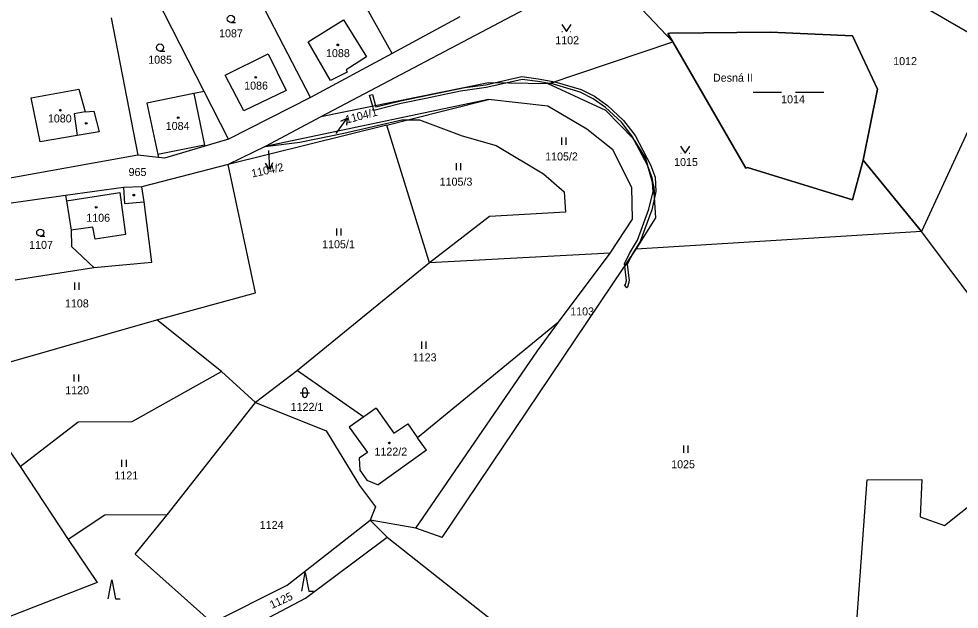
# Model space of a CAD drawing. Extents: x -670359 to -660124, y -978807 to -970072.
# Drawn here: x -669982.9 to -669783.1, y -977781.2 to -977655.6 of the extents above; entities that cross this region are included whole.
import ezdxf

# ---------------------------------------------------------------- set-up
doc = ezdxf.new("R2010")
doc.units = 0
for name, color, linetype in [('Hranice parcel', 7, 'Continuous'), ('Parcelní čísla', 7, 'Continuous'), ('Pop  PČ popisy', 7, 'Continuous'), ('Vnitřní kresba', 7, 'Continuous'), ('Věcná břemena k části', 7, 'Continuous'), ('Značky budov', 7, 'Continuous'), ('Značky kultur', 7, 'Continuous')]:
    doc.layers.add(name, color=color, linetype=linetype)

msp = doc.modelspace()

# ---------------------------------------------------------------- linework, layer by layer
at = {"layer": 'Hranice parcel'}
for p, q in [((-669900.23, -977677.12), (-669883.11, -977672.77)), ((-669913.87, -977679.97), (-669901.49, -977677.14)), ((-669904.67, -977678.25), (-669900.23, -977677.12)), ((-669901.49, -977677.14), (-669900.23, -977677.12)), ((-669900.23, -977677.12), (-669897.75, -977677.09)), ((-669897.75, -977677.09), (-669888.73, -977680.55)), ((-669923.22, -977681.85), (-669913.87, -977679.97)), ((-669888.73, -977680.55), (-669881.48, -977682.58)), ((-669930.56, -977682.8), (-669923.22, -977681.85)), ((-669881.48, -977682.58), (-669871.4, -977688.59)), ((-669871.4, -977688.59), (-669867.03, -977692.44)), ((-669867.03, -977692.44), (-669866.71, -977696.78)), ((-669882.89, -977697.69), (-669895.63, -977707.53)), ((-669866.71, -977696.78), (-669882.89, -977697.69))]:
    msp.add_line(p, q, dxfattribs=at)
for points in [[(-669903.55, -977663.02), (-669919.14, -977635.11)], [(-669773.6, -977662.93), (-669808.82, -977642.52)], [(-669920.94, -977672.36), (-669936.3, -977642.69)], [(-669858.47, -977645.13), (-669843.94, -977660.55)], [(-669943.49, -977671.09), (-669953.69, -977651.05)], [(-669871.55, -977651.52), (-669918.75, -977676.5)], [(-669963.25, -977655.43), (-669957.62, -977684.64)], [(-669921.4, -977660.53), (-669913.91, -977655.85)], [(-669913.91, -977655.85), (-669908.99, -977663.73)], [(-669889.2, -977655.23), (-669903.55, -977663.02)], [(-669823.21, -977658.51), (-669844.56, -977658.72)], [(-669805.77, -977659.28), (-669823.21, -977658.51)], [(-669916.64, -977668.73), (-669921.4, -977660.53)], [(-669870.41, -977669.5), (-669843.94, -977660.55)], [(-669844.56, -977658.72), (-669844.96, -977658.8)], [(-669844.96, -977658.8), (-669843.94, -977660.55)], [(-669828.41, -977687.39), (-669843.94, -977660.55)], [(-669800.43, -977670.6), (-669805.77, -977659.28)], [(-669939.03, -977667.59), (-669929.94, -977663.06)], [(-669929.94, -977663.06), (-669926.06, -977670.87)], [(-669903.55, -977663.02), (-669920.94, -977672.36)], [(-669908.99, -977663.73), (-669913.37, -977666.48)], [(-669773.6, -977662.93), (-669791.07, -977700.83)], [(-669913.37, -977666.48), (-669913.13, -977666.96)], [(-669935.07, -977675.24), (-669939.03, -977667.59)], [(-669913.13, -977666.96), (-669916.64, -977668.73)], [(-669980.27, -977672.47), (-669970.13, -977670.57)], [(-669970.13, -977670.57), (-669968.82, -977675.44)], [(-669883.13, -977669.25), (-669918.75, -977676.5)], [(-669870.41, -977669.5), (-669883.13, -977669.25)], [(-669858.14, -977675.1), (-669870.41, -977669.5)], [(-669978.38, -977681.81), (-669980.27, -977672.47)], [(-669945.73, -977671.55), (-669955.72, -977673.6)], [(-669943.49, -977671.09), (-669945.73, -977671.55)], [(-669938.32, -977681.25), (-669943.49, -977671.09)], [(-669920.94, -977672.36), (-669938.32, -977681.25)], [(-669926.06, -977670.87), (-669935.07, -977675.24)], [(-669803.47, -977685.72), (-669800.43, -977670.6)], [(-669955.72, -977673.6), (-669953.34, -977684.46)], [(-669883.11, -977672.77), (-669930.56, -977682.8)], [(-669870.46, -977674.21), (-669883.11, -977672.77)], [(-669862.2, -977679.12), (-669870.46, -977674.21)], [(-669968.82, -977675.44), (-669966.98, -977675.27)], [(-669966.98, -977675.27), (-669965.84, -977679.66)], [(-669918.75, -977676.5), (-669930.56, -977682.8)], [(-669852.35, -977681.06), (-669858.14, -977675.1)], [(-669904.67, -977678.25), (-669938.45, -977686.61)], [(-669895.63, -977707.53), (-669904.67, -977678.25)], [(-669970.47, -977680.48), (-669978.38, -977681.81)], [(-669965.84, -977679.66), (-669970.47, -977680.48)], [(-669856.66, -977683.48), (-669862.2, -977679.12)], [(-669938.32, -977681.25), (-669951.97, -977685.25)], [(-669849.77, -977685.28), (-669852.35, -977681.06)], [(-669953.34, -977684.46), (-669953.19, -977685.12)], [(-669930.56, -977682.8), (-669938.45, -977686.61)], [(-669852.62, -977691.53), (-669856.66, -977683.48)], [(-669957.62, -977684.64), (-669986.76, -977689.88)], [(-669953.19, -977685.12), (-669957.62, -977684.64)], [(-669951.97, -977685.25), (-669953.19, -977685.12)], [(-669847.98, -977691.34), (-669849.77, -977685.28)], [(-669803.47, -977685.72), (-669805.74, -977694.12)], [(-669791.07, -977700.83), (-669803.47, -977685.72)], [(-669938.45, -977686.61), (-669956.78, -977691.35)], [(-669932.63, -977713.9), (-669938.45, -977686.61)], [(-669828.09, -977687.23), (-669828.41, -977687.39)], [(-669805.74, -977694.12), (-669828.09, -977687.23)], [(-669960.66, -977691.53), (-669972.97, -977693.24)], [(-669956.78, -977691.35), (-669960.66, -977691.53)], [(-669956.24, -977694.54), (-669956.78, -977691.35)], [(-669852.5, -977698.24), (-669852.62, -977691.53)], [(-669847.54, -977697.97), (-669847.98, -977691.34)], [(-669972.97, -977693.24), (-669985.99, -977695.04)], [(-669972.97, -977693.24), (-669972.8, -977694.32)], [(-669972.8, -977694.32), (-669971.8, -977700.55)], [(-669954.65, -977707.4), (-669956.24, -977694.54)], [(-669857.26, -977705.46), (-669852.5, -977698.24)], [(-669851.75, -977704.63), (-669847.54, -977697.97)], [(-669971.8, -977700.55), (-669971.71, -977704.06)], [(-669791.07, -977700.83), (-669851.75, -977704.63)], [(-669764.89, -977735.76), (-669791.07, -977700.83)], [(-669971.71, -977704.06), (-669966.96, -977708.51)], [(-669857.26, -977705.46), (-669895.63, -977707.53)], [(-669892.92, -977765.93), (-669851.75, -977704.63)], [(-669868.22, -977720.15), (-669857.26, -977705.46)], [(-669983.66, -977711.17), (-669966.96, -977708.51)], [(-669966.96, -977708.51), (-669954.65, -977707.4)], [(-669895.63, -977707.53), (-669923.66, -977730.39)], [(-669953.55, -977719.62), (-669932.63, -977713.9)], [(-669996.13, -977731.83), (-669953.55, -977719.62)], [(-669939.81, -977730.65), (-669953.55, -977719.62)], [(-669868.22, -977720.15), (-669898.16, -977744.72)], [(-669872.66, -977726.25), (-669868.22, -977720.15)], [(-669898.53, -977763.96), (-669872.66, -977726.25)], [(-669923.66, -977730.39), (-669932.58, -977737.23)], [(-669923.66, -977730.39), (-669909.56, -977740.23)], [(-669958.79, -977741.23), (-669939.81, -977730.65)], [(-669932.58, -977737.23), (-669939.81, -977730.65)], [(-669993.93, -977734.4), (-669982.65, -977750.8)], [(-669951.41, -977761.08), (-669932.58, -977737.23)], [(-669932.58, -977737.23), (-669917.59, -977743.22)], [(-669907, -977738.39), (-669909.56, -977740.23)], [(-669907, -977738.39), (-669903.19, -977743.73)], [(-669909.56, -977740.23), (-669912.68, -977742.47)], [(-669982.65, -977750.8), (-669970.31, -977741.3)], [(-669970.31, -977741.3), (-669958.79, -977741.23)], [(-669912.68, -977742.47), (-669908.84, -977747.84)], [(-669903.19, -977743.73), (-669900.27, -977741.75)], [(-669900.27, -977741.75), (-669898.16, -977744.72)], [(-669917.59, -977743.22), (-669910.49, -977754.84)], [(-669896.28, -977747.38), (-669898.16, -977744.72)], [(-669908.84, -977747.84), (-669910.58, -977749.07)], [(-669896.28, -977747.38), (-669906.58, -977754.71)], [(-669910.58, -977749.07), (-669910.44, -977751.63)], [(-669982.65, -977750.8), (-669972.41, -977766.32)], [(-669910.44, -977751.63), (-669908.93, -977753.75)], [(-669908.93, -977753.75), (-669906.58, -977754.71)], [(-669805.3, -977790.58), (-669802.62, -977753.64)], [(-669802.62, -977753.64), (-669791.02, -977753.57)], [(-669791.02, -977753.57), (-669791.38, -977761.49)], [(-669910.49, -977754.84), (-669907.11, -977759.38)], [(-669786.17, -977763.37), (-669775.42, -977754.76)], [(-669907.11, -977759.38), (-669908.21, -977762.26)], [(-669964.6, -977761.16), (-669972.41, -977766.32)], [(-669951.41, -977761.08), (-669964.6, -977761.16)], [(-669958.16, -977769.43), (-669951.41, -977761.08)], [(-669925.89, -977776.03), (-669908.21, -977762.26)], [(-669908.21, -977762.26), (-669904.6, -977765.84)], [(-669898.53, -977763.96), (-669908.21, -977762.26)], [(-669791.38, -977761.49), (-669786.17, -977763.37)], [(-669892.92, -977765.93), (-669898.53, -977763.96)], [(-669972.41, -977766.32), (-669966.28, -977775.47)], [(-669921.96, -977778.81), (-669904.6, -977765.84)], [(-669904.6, -977765.84), (-669881.63, -977784.08)], [(-669941.84, -977784.04), (-669958.16, -977769.43)], [(-669966.28, -977775.47), (-669994.9, -977786.6)], [(-669941.84, -977784.04), (-669925.89, -977776.03)], [(-669942.37, -977789.56), (-669921.96, -977778.81)]]:
    msp.add_lwpolyline(points, dxfattribs=at)
at = {"layer": 'Parcelní čísla'}
for p, q in [((-669914.49, -977677.37), (-669913.11, -977676.77)), ((-669928.97, -977686.27), (-669929.65, -977687.6))]:
    msp.add_line(p, q, dxfattribs=at)
for points in [[(-669915.49, -977679.99), (-669913.11, -977676.77), (-669913.28, -977678.26)], [(-669929.86, -977683.61), (-669929.65, -977687.6), (-669930.47, -977686.35)]]:
    msp.add_lwpolyline(points, dxfattribs=at)
at = {"layer": 'Vnitřní kresba'}
for points in [[(-669945.73, -977671.55), (-669943.43, -977682.48)], [(-669968.82, -977675.44), (-669971.14, -977675.85)], [(-669971.14, -977675.85), (-669970.47, -977680.48)], [(-669943.43, -977682.48), (-669953.34, -977684.46)], [(-669960.66, -977691.53), (-669960.48, -977694.89)], [(-669972.8, -977694.32), (-669961.45, -977692.58)], [(-669961.45, -977692.58), (-669960.2, -977701.52)], [(-669960.48, -977694.89), (-669956.24, -977694.54)], [(-669967.17, -977699.96), (-669971.8, -977700.55)], [(-669966.68, -977702.52), (-669967.17, -977699.96)], [(-669960.2, -977701.52), (-669966.68, -977702.52)]]:
    msp.add_lwpolyline(points, dxfattribs=at)
at = {"layer": 'Věcná břemena k části'}
for p, q in [((-669881.89, -977669.27), (-669876.02, -977667.94)), ((-669875.98, -977668.54), (-669879.4, -977669.32)), ((-669876.02, -977667.94), (-669872.54, -977668.38)), ((-669872.63, -977668.98), (-669875.98, -977668.54)), ((-669872.54, -977668.38), (-669868.99, -977669.02)), ((-669901.82, -977673.05), (-669888.16, -977670.27)), ((-669883.58, -977670.28), (-669889.05, -977671)), ((-669888.16, -977670.27), (-669883.68, -977669.68)), ((-669883.68, -977669.68), (-669881.89, -977669.27)), ((-669879.4, -977669.32), (-669883.58, -977670.28)), ((-669870.14, -977669.41), (-669872.63, -977668.98)), ((-669908.36, -977671.86), (-669907.78, -977671.7)), ((-669907.71, -977674.25), (-669908.36, -977671.86)), ((-669907.78, -977671.7), (-669907.13, -977674.13)), ((-669896.45, -977672.57), (-669901.67, -977673.67)), ((-669889.05, -977671), (-669896.45, -977672.57)), ((-669907.48, -977675.11), (-669907.71, -977674.25)), ((-669901.67, -977673.67), (-669907.48, -977675.11)), ((-669907.13, -977674.13), (-669907.06, -977674.39)), ((-669907.06, -977674.39), (-669901.82, -977673.05)), ((-669849.33, -977686.77), (-669852.13, -977681.43)), ((-669848.11, -977692.33), (-669848.24, -977690.47)), ((-669849, -977696.09), (-669848.11, -977692.33)), ((-669847.82, -977693.72), (-669848.42, -977696.27)), ((-669851.41, -977702.7), (-669849, -977696.09)), ((-669848.42, -977696.27), (-669850.87, -977702.96)), ((-669853.13, -977705.52), (-669851.41, -977702.7)), ((-669850.87, -977702.96), (-669852.61, -977705.81)), ((-669854.22, -977707.72), (-669853.13, -977705.52)), ((-669852.61, -977705.81), (-669852.79, -977706.18)), ((-669854.16, -977708.22), (-669854.22, -977707.72))]:
    msp.add_line(p, q, dxfattribs=at)
for points in [[(-669844.96, -977658.8), (-669844.56, -977658.72), (-669823.21, -977658.51), (-669805.77, -977659.28), (-669800.43, -977670.6), (-669803.47, -977685.72), (-669805.74, -977694.12), (-669828.09, -977687.23), (-669828.41, -977687.39), (-669843.94, -977660.55), (-669844.96, -977658.8)], [(-669870.41, -977669.5), (-669843.94, -977660.55), (-669828.41, -977687.39), (-669828.09, -977687.23), (-669805.74, -977694.12), (-669803.47, -977685.72), (-669791.07, -977700.83), (-669851.75, -977704.63), (-669847.54, -977697.97), (-669847.98, -977691.34), (-669849.77, -977685.28), (-669852.35, -977681.06), (-669858.14, -977675.1), (-669870.41, -977669.5)], [(-669870.14, -977669.41), (-669868.99, -977669.02), (-669863.4, -977670.7), (-669860.56, -977672.1), (-669857.84, -977674.04), (-669854.39, -977677.24), (-669851.96, -977680.46), (-669848.7, -977686.69), (-669847.71, -977689.33), (-669847.51, -977692.39)], [(-669868.99, -977669.02), (-669870.14, -977669.41)], [(-669852.46, -977680.78), (-669854.83, -977677.64), (-669858.22, -977674.5), (-669860.86, -977672.62), (-669863.62, -977671.26), (-669869.3, -977669.55), (-669870.14, -977669.41)], [(-669852.13, -977681.43), (-669852.46, -977680.78)], [(-669847.82, -977693.72), (-669847.98, -977691.34), (-669848.31, -977689.45), (-669849.33, -977686.77), (-669849.77, -977685.28), (-669852.13, -977681.43)], [(-669852.13, -977681.43), (-669849.77, -977685.28), (-669849.33, -977686.77)], [(-669848.24, -977690.47), (-669847.98, -977691.34), (-669847.82, -977693.72)], [(-669847.51, -977692.39), (-669847.82, -977693.72)], [(-669854.2, -977712.18), (-669854, -977712.04), (-669853.81, -977711.33), (-669854.16, -977708.22), (-669852.79, -977706.18), (-669853.6, -977707.82), (-669853.21, -977711.37), (-669853.55, -977712.68), (-669853.74, -977712.81), (-669854.2, -977712.18)], [(-669852.79, -977706.18), (-669854.16, -977708.22)]]:
    msp.add_lwpolyline(points, dxfattribs=at)
at = {"layer": 'Značky budov'}
for centre in [(-669915.13, -977661.19), (-669932.56, -977668.09), (-669974.07, -977675.08), (-669949.04, -977676.66), (-669966.45, -977695.72), (-669904.16, -977745.8)]:
    msp.add_circle(centre, 0.175, dxfattribs=at)
at = {"layer": 'Značky kultur'}
for p, q in [((-669937.85, -977656.4), (-669936.85, -977656.4)), ((-669867.5, -977658.35), (-669867.4, -977658.35)), ((-669865.7, -977658.35), (-669865.6, -977658.35)), ((-669952.91, -977662.49), (-669951.91, -977662.49)), ((-669826.87, -977671.22), (-669820.87, -977671.22)), ((-669817.87, -977671.22), (-669811.87, -977671.22)), ((-669867.62, -977680.91), (-669867.62, -977682.41)), ((-669866.62, -977682.41), (-669866.62, -977680.91)), ((-669842.25, -977684.24), (-669842.15, -977684.24)), ((-669840.45, -977684.24), (-669840.35, -977684.24)), ((-669889.95, -977686.3), (-669889.95, -977687.8)), ((-669888.95, -977687.8), (-669888.95, -977686.3)), ((-669915.41, -977700.22), (-669915.41, -977701.72)), ((-669914.41, -977701.72), (-669914.41, -977700.22)), ((-669978.35, -977701.85), (-669977.35, -977701.85)), ((-669971.09, -977711.73), (-669971.09, -977713.23)), ((-669970.09, -977713.23), (-669970.09, -977711.73)), ((-669897.34, -977724.27), (-669897.34, -977725.77)), ((-669896.34, -977725.77), (-669896.34, -977724.27)), ((-669971.18, -977731.25), (-669971.18, -977732.75)), ((-669970.18, -977732.75), (-669970.18, -977731.25)), ((-669923.13, -977735.13), (-669921.13, -977735.13)), ((-669922.63, -977734.63), (-669922.63, -977735.63)), ((-669921.63, -977734.63), (-669921.63, -977735.63)), ((-669841.67, -977746.38), (-669841.67, -977747.88)), ((-669840.67, -977747.88), (-669840.67, -977746.38)), ((-669961.05, -977749.38), (-669961.05, -977750.88)), ((-669960.05, -977750.88), (-669960.05, -977749.38))]:
    msp.add_line(p, q, dxfattribs=at)
for points in [[(-669867.55, -977656.85), (-669866.55, -977658.35), (-669865.55, -977656.85)], [(-669842.3, -977682.74), (-669841.3, -977684.24), (-669840.3, -977682.74)], [(-669922.79, -977777.32), (-669922.04, -977773.32), (-669921.29, -977777.32), (-669920.29, -977777.32)], [(-669963.89, -977778.92), (-669963.14, -977774.92), (-669962.39, -977778.92), (-669961.39, -977778.92)]]:
    msp.add_lwpolyline(points, dxfattribs=at)
for centre, radius in [((-669937.85, -977655.65), 0.75), ((-669952.91, -977661.74), 0.75), ((-669915.13, -977661.19), 0.175), ((-669932.56, -977668.09), 0.175), ((-669974.07, -977675.08), 0.175), ((-669949.04, -977676.66), 0.175), ((-669968.59, -977677.85), 0.175), ((-669958.47, -977693.12), 0.175), ((-669966.45, -977695.72), 0.175), ((-669978.35, -977701.1), 0.75), ((-669904.16, -977745.8), 0.175)]:
    msp.add_circle(centre, radius, dxfattribs=at)
for centre, start, end in [((-669922.13, -977734.63), 0, 180), ((-669922.13, -977735.63), 180, 0)]:
    msp.add_arc(centre, 0.5, start, end, dxfattribs=at)

# ---------------------------------------------------------------- texts
at = {"layer": 'Parcelní čísla'}
for s, height, p in [('1087', 1.7, (-669940.35, -977659.58)), ('1102', 1.7, (-669868.91, -977661.05)), ('1088', 1.7, (-669917.63, -977663.79)), ('1085', 1.7, (-669955.41, -977665.19)), ('1012', 1.7, (-669797.11, -977665.49)), ('1086', 1.7, (-669935.02, -977670.69)), ('1014', 1.7, (-669820.92, -977673.6)), ('1080', 1.7, (-669976.73, -977677.68)), ('1084', 1.7, (-669951.69, -977679.27)), ('1104/1', 0.1, (-669915.49, -977679.99)), ('1104/2', 0.1, (-669929.86, -977683.61)), ('1105/2', 1.7, (-669871.06, -977685.76)), ('1015', 1.7, (-669843.66, -977686.94)), ('965', 1.7, (-669959.58, -977689.06)), ('1105/3', 1.7, (-669893.48, -977691.12)), ('1106', 1.7, (-669968.57, -977698.79)), ('1107', 1.7, (-669980.71, -977704.55)), ('1105/1', 1.7, (-669918.45, -977704.42)), ('1108', 1.7, (-669973.1, -977717)), ('1103', 1.7, (-669865.74, -977718.7)), ('1123', 1.7, (-669899.2, -977728.47)), ('1120', 1.7, (-669973.04, -977735.45)), ('1122/1', 1.7, (-669925.14, -977738.99)), ('1122/2', 1.7, (-669907.33, -977748.5)), ('1025', 1.7, (-669844.28, -977751.19)), ('1121', 1.7, (-669962.59, -977753.58)), ('1124', 1.7, (-669931.71, -977764.09))]:
    msp.add_text(s, height=height, dxfattribs=at).set_placement(p)
for s, rotation, p in [('1104/1', 14.6209, (-669913.28, -977677.94)), ('1104/2', 12.0771, (-669933.3, -977689.38)), ('1125', 24.6051, (-669929.11, -977781.11))]:
    msp.add_text(s, height=1.7, rotation=rotation, dxfattribs=at).set_placement(p)
at = {"layer": 'Pop  PČ popisy'}
msp.add_text('Desná II', height=1.7, dxfattribs=at).set_placement((-669835.4, -977669.01))

doc.saveas('drawing.dxf')
